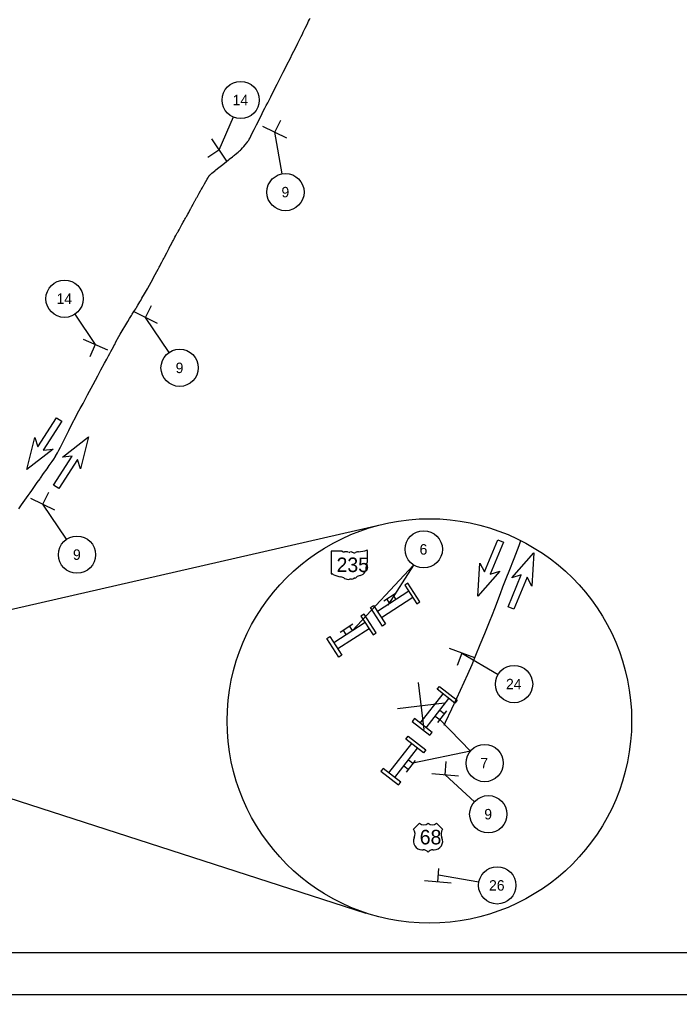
# Model space of a CAD drawing. Extents: x 632.2 to 666.2, y -36.3 to -14.3.
# Drawn here: x 641.29 to 649.19, y -36.3 to -24.64 of the extents above; entities that cross this region are included whole.
import ezdxf

# ---------------------------------------------------------------- set-up
doc = ezdxf.new("R2010")
doc.units = 0
for name, color, linetype in [('Default', 7, 'Continuous'), ('GM_X_County_Subdivision', 7, 'Continuous'), ('GM_X_County_Subdivision_Text', 7, 'Continuous'), ('GM_X_Township_Road_Text', 7, 'Continuous'), ('GM_X_Township_Subdivision', 7, 'Continuous'), ('MT_P_Cells', 7, 'Continuous'), ('SH_Border', 7, 'Continuous'), ('SH_Cut_Line', 7, 'Continuous'), ('SH_Text', 7, 'Continuous'), ('SN_P_Signs', 7, 'Continuous')]:
    doc.layers.add(name, color=color, linetype=linetype)

msp = doc.modelspace()

# ---------------------------------------------------------------- linework, layer by layer
at = {"layer": 'Default'}
for centre in [(643.938, -25.604), (644.474, -26.706), (641.831, -27.981), (643.208, -28.807), (646.128, -30.978), (641.98, -31.042), (647.208, -32.59), (646.857, -33.535), (646.9, -34.146), (647.007, -34.997)]:
    msp.add_circle(centre, 0.223, dxfattribs=at)
at = {"layer": 'GM_X_County_Subdivision'}
for p, q in [((646.078, -34.253), (646.006, -34.325)), ((646.354, -34.325), (646.281, -34.253)), ((646.107, -34.572), (646.122, -34.572)), ((646.238, -34.572), (646.252, -34.572))]:
    msp.add_line(p, q, dxfattribs=at)
for centre, radius, start, end in [((646.129, -34.201), 0.0725, 225.573, 314.427), ((646.231, -34.201), 0.0725, 225.573, 314.427), ((645.923, -34.384), 0.102, 334.5471, 35.0009), ((646.437, -34.384), 0.102, 144.9991, 205.4529), ((646.106, -34.47), 0.102, 154.8319, 270.6383), ((646.253, -34.47), 0.102, 269.3617, 25.1681), ((646.122, -34.644), 0.0725, 36.8699, 90), ((646.238, -34.644), 0.0725, 90, 143.1301)]:
    msp.add_arc(centre, radius, start, end, dxfattribs=at)
at = {"layer": 'GM_X_County_Subdivision_Text'}
for p, q in [((646.062, -32.571), (646.129, -33.134)), ((646.377, -32.819), (645.814, -32.886)), ((646.096, -32.852), (646.096, -32.852))]:
    msp.add_line(p, q, dxfattribs=at)
at = {"layer": 'GM_X_Township_Road_Text'}
for p, q in [((645.019, -31.005), (645.019, -31.269)), ((645.151, -31), (645.023, -31)), ((645.454, -31.132), (645.454, -30.993)), ((645.454, -31.132), (645.454, -31.132))]:
    msp.add_line(p, q, dxfattribs=at)
for centre, major_axis, start_param, end_param in [((645.024, -31.004), (0.00504, 0), 1.712693, 3.28349), ((645.181, -30.969), (0.0489, 0), 4.042523, 4.731795), ((645.197, -31.148), (0.175, 0), 1.404758, 1.657858), ((645.237, -31.003), (0.0141, 0), 3.836095, 5.185415), ((645.258, -31.033), (0.0293, 0), 0.950623, 2.079405), ((645.296, -30.991), (0.0353, 0), 4.081561, 5.145723), ((645.358, -31.081), (0.0928, 0), 1.699011, 2.107814), ((645.299, -30.64), (0.461, 0), 4.814394, 5.042369), ((645.449, -30.993), (0.00484, 0), 6.141152, 7.989035), ((645.449, -31.132), (0.00518, 0), 5.05454, 6.418171), ((645.325, -31.207), (0.115, 0), 5.101752, 6.440018), ((645.471, -31.189), (0.0327, 0), 2.387724, 3.262537), ((645.453, -31.142), (0.0075, 0), 1.883978, 3.671073), ((645.405, -31.159), (0.045, 0), 5.934695, 6.695948), ((645.024, -31.269), (0.00508, 0), 3.00124, 4.508301), ((645.025, -31.242), (0.0388, 0), 4.665946, 4.897461), ((645.033, -31.284), (0.014, 0), 0.519207, 1.627899), ((645.209, -31.047), (0.333, 0), 4.195997, 4.488961), ((645.11, -31.387), (0.104, 0), 0.823519, 1.323587), ((645.223, -31.285), (0.0661, 0), 4.026481, 4.996735), ((645.261, -31.377), (0.0544, 0), 1.495662, 1.94098), ((645.266, -31.305), (0.0352, 0), 4.691044, 5.507374), ((645.298, -31.331), (0.00992, 0), 1.147584, 2.315152), ((645.294, -31.294), (0.0373, 0), 4.937069, 5.64225), ((645.374, -31.343), (0.0632, 0), 1.647645, 2.488434)]:
    msp.add_ellipse(centre, major_axis=major_axis, ratio=0.8, start_param=start_param, end_param=end_param, dxfattribs=at)
at = {"layer": 'GM_X_Township_Subdivision'}
for p, q in [((641.512, -29.753), (641.736, -29.406)), ((641.799, -29.447), (641.575, -29.793)), ((641.736, -29.406), (641.799, -29.447)), ((641.767, -29.427), (641.767, -29.427)), ((641.381, -30.025), (641.475, -29.639)), ((641.475, -29.639), (641.512, -29.753)), ((641.806, -29.876), (642.119, -29.631)), ((642.119, -29.631), (642.024, -30.017)), ((642.119, -29.631), (642.119, -29.631)), ((641.694, -29.781), (641.381, -30.025)), ((641.575, -29.793), (641.694, -29.781)), ((641.7, -30.209), (641.924, -29.863)), ((641.987, -29.904), (641.763, -30.25)), ((641.924, -29.863), (641.806, -29.876)), ((642.024, -30.017), (641.987, -29.904)), ((641.381, -30.025), (641.381, -30.025)), ((641.763, -30.25), (641.7, -30.209)), ((641.732, -30.23), (641.732, -30.23)), ((646.854, -31.246), (647.013, -30.865)), ((647.082, -30.894), (646.924, -31.275)), ((647.013, -30.865), (647.082, -30.894)), ((647.047, -30.88), (647.047, -30.88)), ((647.181, -31.317), (647.445, -31.021)), ((647.445, -31.021), (647.421, -31.417)), ((647.445, -31.021), (647.445, -31.021)), ((646.774, -31.538), (646.798, -31.142)), ((647.038, -31.241), (646.774, -31.538)), ((646.798, -31.142), (646.854, -31.246)), ((646.924, -31.275), (647.038, -31.241)), ((647.137, -31.665), (647.295, -31.284)), ((647.295, -31.284), (647.181, -31.317)), ((647.364, -31.312), (647.206, -31.693)), ((647.421, -31.417), (647.364, -31.312)), ((646.774, -31.538), (646.774, -31.538)), ((647.206, -31.693), (647.137, -31.665)), ((647.171, -31.679), (647.171, -31.679))]:
    msp.add_line(p, q, dxfattribs=at)
at = {"layer": 'MT_P_Cells'}
for p, q in [((645.948, -31.48), (645.575, -31.722)), ((645.996, -31.555), (645.624, -31.797)), ((645.651, -31.594), (645.8, -31.497)), ((645.724, -31.625), (645.688, -31.569)), ((645.799, -31.577), (645.763, -31.521)), ((645.786, -31.638), (645.786, -31.638)), ((645.426, -31.853), (645.053, -32.095)), ((645.474, -31.928), (645.101, -32.17)), ((645.128, -31.967), (645.278, -31.87)), ((645.202, -31.998), (645.166, -31.942)), ((645.277, -31.95), (645.24, -31.894)), ((645.264, -32.011), (645.264, -32.011)), ((646.087, -33.058), (646.36, -32.707)), ((646.157, -33.112), (646.43, -32.761)), ((646.259, -32.91), (646.259, -32.91)), ((646.266, -32.972), (646.319, -33.013)), ((646.401, -32.908), (646.292, -33.048)), ((646.321, -32.902), (646.374, -32.943)), ((645.711, -33.652), (645.984, -33.301)), ((645.782, -33.707), (646.054, -33.356)), ((645.883, -33.504), (645.883, -33.504)), ((645.891, -33.566), (645.943, -33.607)), ((646.025, -33.502), (645.916, -33.642)), ((645.945, -33.496), (645.998, -33.537))]:
    msp.add_line(p, q, dxfattribs=at)
for points in [[(646.082, -31.605), (645.937, -31.381), (645.9, -31.406), (646.045, -31.629)], [(645.635, -31.895), (645.49, -31.672), (645.527, -31.648), (645.672, -31.871)], [(645.56, -31.978), (645.415, -31.754), (645.377, -31.779), (645.523, -32.002)], [(645.112, -32.268), (644.967, -32.045), (645.005, -32.021), (645.15, -32.244)], [(646.317, -32.617), (646.528, -32.781), (646.5, -32.816), (646.29, -32.652)], [(645.99, -33.038), (646.2, -33.202), (646.228, -33.167), (646.017, -33.003)], [(645.941, -33.212), (646.152, -33.375), (646.125, -33.41), (645.914, -33.247)], [(645.614, -33.633), (645.825, -33.796), (645.852, -33.761), (645.641, -33.598)]]:
    msp.add_lwpolyline(points, close=True, dxfattribs=at)
at = {"layer": 'SH_Border'}
msp.add_lwpolyline([(633.687, -14.802), (665.687, -14.802), (665.687, -35.802), (633.687, -35.802)], close=True, dxfattribs=at)
at = {"layer": 'SH_Cut_Line'}
msp.add_lwpolyline([(632.187, -36.302), (666.187, -36.302), (666.187, -14.302), (632.187, -14.302)], close=True, dxfattribs=at)
at = {"layer": 'SH_Text'}
for p, q in [((643.848, -25.809), (643.677, -26.202)), ((644.435, -26.486), (644.347, -25.99)), ((641.956, -28.166), (642.199, -28.527)), ((643.083, -28.622), (642.801, -28.205)), ((641.855, -30.857), (641.573, -30.439)), ((639.945, -31.982), (645.642, -30.676)), ((646.007, -31.166), (645.277, -31.95)), ((646.007, -31.166), (645.699, -31.645)), ((646.584, -32.218), (647.017, -32.476)), ((646.686, -33.391), (646.319, -33.013)), ((646.686, -33.391), (645.998, -33.537)), ((639.878, -33.535), (645.435, -35.328)), ((646.735, -33.996), (646.384, -33.677)), ((646.787, -34.959), (646.304, -34.876))]:
    msp.add_line(p, q, dxfattribs=at)
for points in [[(644.677, -24.816), (644.687, -24.794), (644.711, -24.746), (644.732, -24.702), (644.751, -24.663), (644.761, -24.643), (644.77, -24.626)], [(644.012, -26.115), (644.022, -26.101), (644.027, -26.094), (644.034, -26.083), (644.04, -26.073), (644.05, -26.055), (644.06, -26.035), (644.081, -25.994), (644.1, -25.956), (644.112, -25.932), (644.129, -25.899), (644.142, -25.873), (644.167, -25.823), (644.186, -25.785), (644.205, -25.747), (644.229, -25.7), (644.245, -25.669), (644.261, -25.637), (644.277, -25.606), (644.297, -25.565), (644.314, -25.532), (644.334, -25.494), (644.356, -25.451), (644.374, -25.415), (644.394, -25.375), (644.418, -25.328), (644.447, -25.271), (644.478, -25.21), (644.496, -25.174), (644.529, -25.11), (644.56, -25.048), (644.588, -24.993), (644.623, -24.923), (644.662, -24.846), (644.677, -24.816)], [(643.839, -26.284), (643.851, -26.273), (643.863, -26.264), (643.872, -26.256), (643.874, -26.255), (643.908, -26.226), (643.926, -26.21), (643.936, -26.202), (643.942, -26.195), (643.959, -26.178), (643.974, -26.162), (643.992, -26.141), (644.012, -26.115)], [(643.692, -26.399), (643.724, -26.374), (643.767, -26.34), (643.793, -26.32), (643.795, -26.319), (643.802, -26.313), (643.839, -26.284)], [(643.557, -26.517), (643.558, -26.515), (643.561, -26.511), (643.562, -26.509), (643.563, -26.508), (643.566, -26.505), (643.568, -26.503), (643.57, -26.5), (643.572, -26.498), (643.576, -26.495), (643.581, -26.49), (643.592, -26.481), (643.598, -26.476), (643.601, -26.474), (643.632, -26.448), (643.64, -26.441), (643.677, -26.411), (643.692, -26.399)], [(643.391, -26.811), (643.393, -26.807), (643.41, -26.776), (643.416, -26.766), (643.428, -26.743), (643.442, -26.718), (643.458, -26.691), (643.467, -26.675), (643.469, -26.672), (643.476, -26.66), (643.487, -26.64), (643.493, -26.629), (643.497, -26.621), (643.507, -26.605), (643.522, -26.577), (643.538, -26.549), (643.544, -26.54), (643.548, -26.532), (643.549, -26.53), (643.551, -26.526), (643.553, -26.524), (643.554, -26.522), (643.556, -26.518), (643.557, -26.517)], [(643.176, -27.202), (643.18, -27.194), (643.185, -27.186), (643.189, -27.177), (643.201, -27.155), (643.213, -27.133), (643.232, -27.099), (643.236, -27.092), (643.251, -27.066), (643.262, -27.045), (643.271, -27.03), (643.277, -27.017), (643.287, -27), (643.289, -26.997), (643.305, -26.968), (643.316, -26.948), (643.339, -26.905), (643.34, -26.903), (643.355, -26.876), (643.37, -26.849), (643.375, -26.84), (643.391, -26.811)], [(642.916, -27.691), (642.936, -27.654), (642.952, -27.626), (642.964, -27.603), (642.97, -27.591), (642.981, -27.57), (642.996, -27.543), (642.996, -27.543), (643.004, -27.527), (643.011, -27.511), (643.018, -27.5), (643.027, -27.482), (643.053, -27.431), (643.081, -27.377), (643.084, -27.371), (643.097, -27.346), (643.127, -27.292), (643.134, -27.279), (643.141, -27.266), (643.152, -27.245), (643.164, -27.224), (643.176, -27.202)], [(642.743, -28), (642.757, -27.976), (642.788, -27.923), (642.823, -27.861), (642.826, -27.855), (642.866, -27.782), (642.916, -27.691)], [(642.633, -28.18), (642.641, -28.167), (642.662, -28.133), (642.682, -28.101), (642.691, -28.086), (642.707, -28.059), (642.732, -28.018), (642.743, -28)], [(642.589, -28.252), (642.61, -28.218), (642.633, -28.18)], [(641.285, -30.493), (641.317, -30.447), (641.337, -30.418), (641.358, -30.388), (641.395, -30.336), (641.419, -30.302), (641.439, -30.275), (641.448, -30.261), (641.497, -30.192), (641.505, -30.18), (641.538, -30.133), (641.544, -30.126), (641.581, -30.073), (641.623, -30.014), (641.649, -29.977), (641.683, -29.928), (641.702, -29.899), (641.722, -29.867), (641.723, -29.864), (641.746, -29.824), (641.764, -29.792), (641.782, -29.758), (641.82, -29.683), (641.824, -29.675), (641.847, -29.628), (641.883, -29.556), (641.924, -29.475), (641.965, -29.395), (641.988, -29.351), (642.02, -29.293), (642.052, -29.232), (642.107, -29.13), (642.175, -29.005), (642.229, -28.904), (642.267, -28.833), (642.311, -28.752), (642.337, -28.703), (642.352, -28.673), (642.358, -28.663), (642.373, -28.635), (642.386, -28.611), (642.401, -28.583), (642.415, -28.557), (642.43, -28.529), (642.431, -28.528), (642.446, -28.498), (642.481, -28.433), (642.498, -28.403), (642.532, -28.345), (642.551, -28.314), (642.589, -28.252)], [(646.371, -33.08), (646.388, -33.045), (646.463, -32.885), (646.523, -32.758), (646.568, -32.662), (646.654, -32.472), (646.706, -32.354), (646.736, -32.284), (646.761, -32.223), (646.796, -32.136), (646.803, -32.118), (646.858, -31.983), (646.914, -31.847), (646.949, -31.758), (646.977, -31.684), (647.046, -31.505), (647.076, -31.427), (647.123, -31.308), (647.149, -31.239), (647.208, -31.087), (647.269, -30.931), (647.291, -30.874)]]:
    msp.add_lwpolyline(points, dxfattribs=at)
msp.add_circle((646.196, -33.031), 2.419, dxfattribs=at)
at = {"layer": 'SN_P_Signs'}
for p, q in [((644.347, -25.99), (644.418, -25.846)), ((644.491, -26.06), (644.203, -25.919)), ((643.588, -26.069), (643.767, -26.334)), ((643.677, -26.202), (643.545, -26.291)), ((642.801, -28.205), (642.871, -28.062)), ((642.944, -28.276), (642.657, -28.135)), ((642.053, -28.463), (642.346, -28.591)), ((642.199, -28.527), (642.135, -28.674)), ((641.573, -30.439), (641.643, -30.296)), ((641.716, -30.51), (641.429, -30.369)), ((646.434, -32.162), (646.735, -32.273)), ((646.584, -32.218), (646.529, -32.368)), ((646.384, -33.677), (646.397, -33.517)), ((646.544, -33.69), (646.225, -33.664)), ((646.298, -34.956), (646.31, -34.796)), ((646.457, -34.969), (646.138, -34.943))]:
    msp.add_line(p, q, dxfattribs=at)

# ---------------------------------------------------------------- texts
at = {"layer": 'Default'}
for s, p in [('14', (643.842, -25.667)), ('9', (644.426, -26.768)), ('14', (641.735, -28.043)), ('9', (643.16, -28.87)), ('9', (641.932, -31.104)), ('6', (646.078, -31.041)), ('24', (647.112, -32.652)), ('7', (646.805, -33.597)), ('9', (646.852, -34.208)), ('26', (646.909, -35.06))]:
    msp.add_text(s, height=0.125, dxfattribs=at).set_placement(p)
at = {"layer": 'GM_X_County_Subdivision'}
msp.add_text('68', height=0.174, dxfattribs=at).set_placement((646.08, -34.507))
at = {"layer": 'GM_X_Township_Road_Text'}
msp.add_text('235', height=0.174, dxfattribs=at).set_placement((645.085, -31.25))

doc.saveas('drawing.dxf')
